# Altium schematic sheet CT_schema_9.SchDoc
size 226 x 144 mm
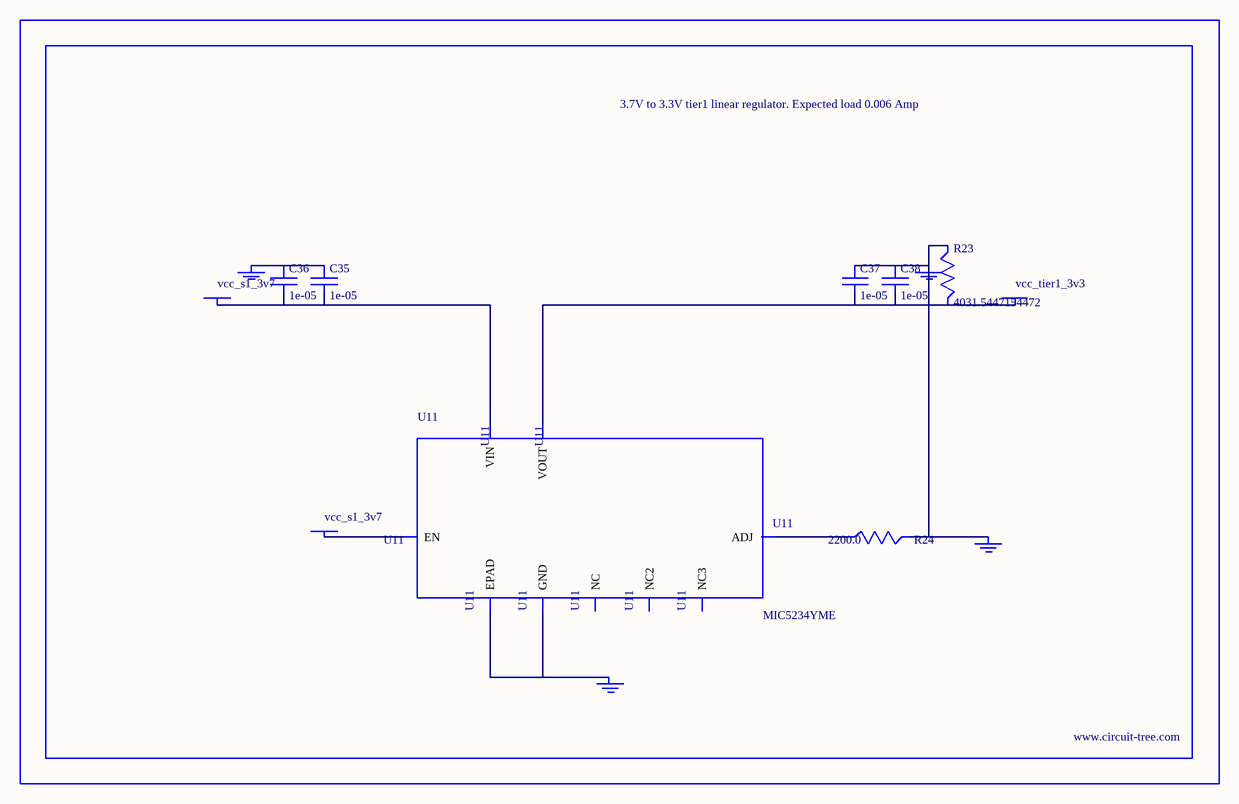
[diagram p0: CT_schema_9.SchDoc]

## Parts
BORDER8  (no value)
C35  1e-05  [C1210]
C36  1e-05  [C1210]
C37  1e-05  [C1210]
C38  1e-05  [C1210]
GND_INSTANCE_8_0  (no value)
GND_INSTANCE_8_1  (no value)
GND_INSTANCE_8_2  (no value)
GND_INSTANCE_8_3  (no value)
POWER_INSTANCE_8_0  vcc_tier1_3v3
POWER_INSTANCE_8_1  vcc_s1_3v7
POWER_INSTANCE_8_2  vcc_s1_3v7
R23  4031.5447154472  [R0603]
R24  2200.0  [R0603]
U11  MIC5234YME  [SOIC-8_EP]

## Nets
NetC35_1: C35.1 C36.1 GND_INSTANCE_8_3.0(GND)
NetC35_2: C35.2 C36.2 POWER_INSTANCE_8_2.0(PWR) U11.8(VIN)
NetC37_1: C37.1 C38.1 GND_INSTANCE_8_0.0(GND) GND_INSTANCE_8_1.0(GND) R23.1 R24.2
NetC37_2: C37.2 C38.2 POWER_INSTANCE_8_0.0(PWR) R23.2 U11.1(VOUT)
NetGND_INSTANCE_8_2_0: GND_INSTANCE_8_2.0(GND) U11.7(GND) U11.EPAD
NetPOWER_INSTANCE_8_1_0: POWER_INSTANCE_8_1.0(PWR) U11.5(EN)
NetR24_1: R24.1 U11.4(ADJ)

Not connected (* = marked no-connect by the designer): U11 2(NC) 3(NC2) 6(NC3)

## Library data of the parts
BORDER8 = BORDER_PAGE8
C35-C38 = C1210C106K5PACTU
GND_INSTANCE_8_0-GND_INSTANCE_8_3 = GND
POWER_INSTANCE_8_0-POWER_INSTANCE_8_2 = PWR
R23 = R23
R24 = RC0603JR-072K2L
